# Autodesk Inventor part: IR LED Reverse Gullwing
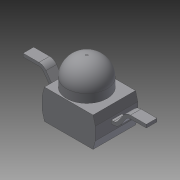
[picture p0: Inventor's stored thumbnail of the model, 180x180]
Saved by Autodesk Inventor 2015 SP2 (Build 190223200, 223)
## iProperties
Created: 2015-09
Part Number: IR LED Reverse Gullwing
Material: Allgemein
Document SubType Name: Modeling
Designer: rYan
Density: 1 g/cm^3
Appearance: Vorgabe
Author: rYan
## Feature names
1. Extrusion1
2. Extrusion2
3. Rundung1 [Fillet]
4. Sweeping1
5. Spiegeln1 [Mirror]
6. Fase1 [Chamfer]
7. Fase2 [Chamfer]
## Parameters: d0 = 2.5 mm, d1 = 2 mm, d2 = 1.4 mm, d3 = 0, d4 = 1.9 mm, d5 = 1.1 mm, d6 = 1.3 mm, d7 = 0, d8 = 0.9 mm, d9 = 55 deg, d10 = 2.9 mm, d11 = 2.15 mm, d12 = 0.05 mm, d13 = 0.6 mm, d14 = 0.15 mm, d15 = 0.5 mm, d16 = 0, d17 = 0, d18 = 0.4 mm, d19 = 2 mm, d20 = 15 deg, d21 = 0.4 mm, d22 = 2 mm, d23 = 15 deg
